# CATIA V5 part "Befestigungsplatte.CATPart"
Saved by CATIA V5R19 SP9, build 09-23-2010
Part number: Befestigungsplatte
Bounding box of the stored display mesh (mm): x -55.527 to 75.718, y -46.972 to 50.987, z 0 to 20
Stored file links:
  D:\Temporäre Sachen\Lasermodul KY-008 with mounting for adjustment\Befestigungsplatte.CATPart
  E:\Markus\Adruino\Tischkicker\CAD Modell\Laser Modul Einsteller.CATPart
  d:\Program Files\Dassault Systemes\B19\win_b64\reffiles\standard\MetricThickPitch.txt
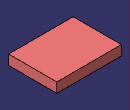
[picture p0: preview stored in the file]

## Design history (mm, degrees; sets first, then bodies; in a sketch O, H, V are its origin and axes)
Set1 "set"
  Sketch1 on xy-plane, origin (0, 0, 0), H (1, 0, 0), V (0, 1, 0)
    point P1 (-19, 12)
    point P2 (-9, -14)
    distance H P1 = 12
    distance P1 V = 19
    distance P2 H = 14
    distance P2 V = 9
Body1 (main body)
  Sketch2 on xy-plane, origin (0, 0, 0), H (1, 0, 0), V (0, 1, 0)
    line L1 (-55.5268, 50.9866) -> (75.7184, 50.9866)
    line L2 (75.7184, 50.9866) -> (75.7184, -46.9719)
    line L3 (75.7184, -46.9719) -> (-55.5268, -46.9719)
    line L4 (-55.5268, -46.9719) -> (-55.5268, 50.9866)
    horizontal: L1 H, L3 H
    vertical: L2 V, L4 V
  Pad1: profile Sketch2, direction (0, 0, 1), length 20
  Sketch3 on start face of Pad1, origin (-19, 12, 0), H (1, 0, 0), V (0, 1, 0)
    point P1 (0, 0)
    reference projected point E1 (0, 0) from Sketch1.P1
    coincidence: E1 P1
  Hole1: placed by Sketch3, at (-19, 12, 0) direction (0, 0, 1), diameter 2.459, depth 16, threaded "M3", thread diameter 3, thread depth 10, pitch 0.5
  UserPattern1: of Hole1, copies 2, at the points of Sketch1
